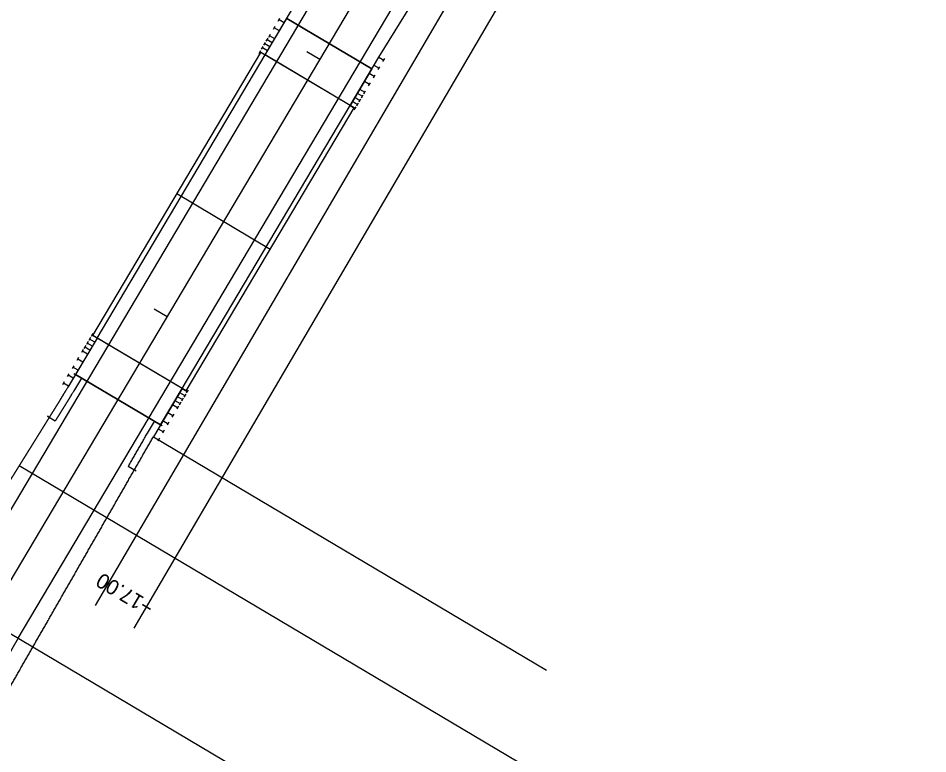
# Model space of a CAD drawing. Extents: x 2138032 to 2141863, y 405316 to 411953.
# Drawn here: x 2140967.3 to 2141271.2, y 410155 to 410400.8 of the extents above; entities that cross this region are included whole.
import ezdxf

# ---------------------------------------------------------------- set-up
doc = ezdxf.new("R2010")
doc.units = 0
for name, color, linetype in [('Prop Approach Slab', 7, 'Continuous'), ('Prop Approach Slab Hatching', 7, 'Continuous'), ('Prop Dimension Text', 7, 'Continuous'), ('Prop EOT', 7, 'Continuous'), ('Prop Guardrail', 7, 'Continuous'), ('Prop Horizontal Alignment', 7, 'Continuous'), ('Prop Horizontal Alignment Station Label', 7, 'Continuous'), ('Prop Horizontal Alignment Tick Small', 7, 'Continuous'), ('Prop Roadway Bridge', 7, 'Continuous'), ('Prop SBG', 7, 'Continuous'), ('Prop Structure Anchor Unit CELL', 7, 'Continuous'), ('Scratch_Level_3', 7, 'Continuous'), ('Scratch_Level_6', 7, 'Continuous')]:
    doc.layers.add(name, color=color, linetype=linetype)

msp = doc.modelspace()

# ---------------------------------------------------------------- linework, layer by layer
at = {"layer": 'Prop Approach Slab'}
for p, q in [((2141049.79, 410388.53), (2141057.02, 410400.71)), ((2141085.4, 410383.87), (2141057.02, 410400.71)), ((2141078.17, 410371.68), (2141085.4, 410383.87)), ((2140993.64, 410293.93), (2140986.41, 410281.75)), ((2141014.79, 410264.9), (2140986.41, 410281.75)), ((2141022.02, 410277.09), (2141014.79, 410264.9))]:
    msp.add_line(p, q, dxfattribs=at)
at = {"layer": 'Prop Approach Slab Hatching'}
for points in [[(2141049.79, 410388.53), (2141057.02, 410400.71), (2141085.4, 410383.87), (2141078.17, 410371.68)], [(2141014.79, 410264.9), (2141022.02, 410277.09), (2140993.64, 410293.93), (2140986.41, 410281.75)]]:
    msp.add_lwpolyline(points, close=True, dxfattribs=at)
at = {"layer": 'Prop EOT'}
for p, q in [((2140946.62, 410205.9), (2141250.61, 410718.06)), ((2140967.26, 410193.65), (2141271.25, 410705.81))]:
    msp.add_line(p, q, dxfattribs=at)
msp.add_arc((2150502.22, 404534.29), 11088, 149.309258, 150.70339, dxfattribs=at)
at = {"layer": 'Prop Guardrail'}
msp.add_line((2141087.74, 410387.81), (2141124.01, 410446.23), dxfattribs=at)
msp.add_open_spline([(2140984.07, 410277.81), (2140983.8, 410277.36), (2140983.52, 410276.92), (2140983.24, 410276.47), (2140983.1, 410276.25), (2140982.96, 410276.02), (2140982.83, 410275.8), (2140982.69, 410275.58), (2140982.55, 410275.35), (2140982.41, 410275.13), (2140982.27, 410274.91), (2140982.13, 410274.68), (2140981.99, 410274.46), (2140981.86, 410274.24), (2140981.72, 410274.01), (2140981.58, 410273.79), (2140981.44, 410273.57), (2140981.3, 410273.34), (2140981.16, 410273.12), (2140981.02, 410272.9), (2140980.89, 410272.67), (2140980.75, 410272.45), (2140980.61, 410272.23), (2140980.47, 410272), (2140980.33, 410271.78), (2140980.19, 410271.56), (2140980.05, 410271.33), (2140979.91, 410271.11), (2140979.78, 410270.89), (2140979.64, 410270.66), (2140979.5, 410270.44), (2140979.36, 410270.22), (2140979.22, 410270), (2140979.08, 410269.77), (2140978.94, 410269.55), (2140978.81, 410269.33), (2140978.67, 410269.1), (2140978.53, 410268.88), (2140978.39, 410268.66), (2140978.25, 410268.43), (2140978.11, 410268.21), (2140977.97, 410267.99), (2140977.84, 410267.76), (2140977.7, 410267.54), (2140977.56, 410267.32), (2140977.42, 410267.09), (2140977.28, 410266.87), (2140977.14, 410266.65), (2140977, 410266.42), (2140976.86, 410266.2), (2140976.73, 410265.98), (2140976.59, 410265.75), (2140976.45, 410265.53), (2140976.31, 410265.31), (2140976.17, 410265.08), (2140976.03, 410264.86), (2140975.89, 410264.64), (2140975.76, 410264.41), (2140975.62, 410264.19), (2140975.48, 410263.97), (2140975.34, 410263.74), (2140975.2, 410263.52), (2140975.06, 410263.3), (2140974.92, 410263.07), (2140974.79, 410262.85), (2140974.65, 410262.63), (2140974.51, 410262.4), (2140974.37, 410262.18), (2140974.23, 410261.96), (2140974.09, 410261.73), (2140973.95, 410261.51), (2140973.81, 410261.29), (2140973.68, 410261.06), (2140973.54, 410260.84), (2140973.4, 410260.62), (2140973.26, 410260.39), (2140973.12, 410260.17), (2140972.98, 410259.95), (2140972.84, 410259.72), (2140972.71, 410259.5), (2140972.57, 410259.28), (2140972.43, 410259.05), (2140972.29, 410258.83), (2140972.15, 410258.61), (2140972.01, 410258.38), (2140971.87, 410258.16), (2140971.74, 410257.94), (2140971.6, 410257.71), (2140971.46, 410257.49), (2140971.32, 410257.27), (2140971.18, 410257.04), (2140971.04, 410256.82), (2140970.9, 410256.6), (2140970.76, 410256.38), (2140970.63, 410256.15), (2140970.49, 410255.93), (2140970.35, 410255.71), (2140970.21, 410255.48), (2140970.07, 410255.26), (2140969.93, 410255.04), (2140969.79, 410254.81), (2140969.66, 410254.59), (2140969.52, 410254.37), (2140969.38, 410254.14), (2140969.24, 410253.92), (2140969.1, 410253.7), (2140968.96, 410253.47), (2140968.82, 410253.25), (2140968.69, 410253.03), (2140968.55, 410252.8), (2140968.41, 410252.58), (2140968.27, 410252.36), (2140968.13, 410252.13), (2140967.99, 410251.91), (2140967.85, 410251.69), (2140967.71, 410251.46), (2140967.58, 410251.24), (2140967.44, 410251.02), (2140967.3, 410250.79), (2140967.16, 410250.57), (2140967.02, 410250.35), (2140966.88, 410250.12), (2140966.74, 410249.9), (2140966.61, 410249.68), (2140966.47, 410249.45), (2140966.33, 410249.23), (2140966.19, 410249.01), (2140966.05, 410248.78), (2140965.91, 410248.56), (2140965.77, 410248.34), (2140965.64, 410248.11), (2140965.5, 410247.89), (2140965.36, 410247.67), (2140965.22, 410247.44), (2140965.08, 410247.22), (2140964.94, 410247), (2140964.8, 410246.77), (2140964.67, 410246.55), (2140964.53, 410246.33), (2140964.39, 410246.1), (2140964.25, 410245.88), (2140964.11, 410245.66), (2140963.97, 410245.43), (2140963.83, 410245.21), (2140963.69, 410244.99), (2140963.56, 410244.76), (2140963.42, 410244.54), (2140963.28, 410244.32), (2140963.14, 410244.09), (2140963, 410243.87), (2140962.86, 410243.65), (2140962.72, 410243.43), (2140962.59, 410243.2), (2140962.45, 410242.98), (2140962.31, 410242.76), (2140962.17, 410242.53), (2140962.03, 410242.31), (2140961.89, 410242.09), (2140961.75, 410241.86), (2140961.62, 410241.64), (2140961.48, 410241.42), (2140961.34, 410241.19), (2140961.2, 410240.97), (2140961.06, 410240.75), (2140960.92, 410240.52), (2140960.78, 410240.3), (2140960.64, 410240.08), (2140960.51, 410239.85), (2140960.37, 410239.63), (2140960.23, 410239.41), (2140960.09, 410239.18), (2140959.95, 410238.96), (2140959.81, 410238.74), (2140959.67, 410238.51), (2140959.54, 410238.29), (2140959.4, 410238.07), (2140959.26, 410237.84), (2140959.12, 410237.62), (2140958.98, 410237.4), (2140958.84, 410237.17), (2140958.7, 410236.95), (2140958.57, 410236.73), (2140958.43, 410236.5), (2140958.29, 410236.28), (2140958.15, 410236.06), (2140958.01, 410235.83), (2140957.87, 410235.61), (2140957.73, 410235.39), (2140957.59, 410235.16), (2140957.46, 410234.94), (2140957.32, 410234.72), (2140957.18, 410234.49), (2140957.04, 410234.27), (2140956.9, 410234.05), (2140956.76, 410233.82), (2140956.62, 410233.6), (2140956.49, 410233.38), (2140956.35, 410233.15), (2140956.21, 410232.93), (2140956.07, 410232.71), (2140955.93, 410232.48), (2140955.79, 410232.26), (2140955.65, 410232.04), (2140955.52, 410231.81), (2140955.38, 410231.59), (2140955.24, 410231.37), (2140955.1, 410231.14), (2140954.96, 410230.92), (2140954.82, 410230.7), (2140954.68, 410230.48), (2140954.54, 410230.25), (2140954.41, 410230.03), (2140954.27, 410229.81), (2140954.13, 410229.58), (2140953.99, 410229.36), (2140953.85, 410229.14), (2140953.71, 410228.91), (2140953.57, 410228.69), (2140953.44, 410228.47), (2140953.3, 410228.24)], degree=3, dxfattribs=at)
for points in [[(2140983.7, 410210.8), (2140984.08, 410211.48), (2140984.47, 410212.16), (2140984.86, 410212.84), (2140985.25, 410213.52), (2140985.64, 410214.19), (2140986.03, 410214.87), (2140986.42, 410215.55), (2140986.81, 410216.23), (2140987.19, 410216.91), (2140987.58, 410217.58), (2140987.97, 410218.26), (2140988.36, 410218.94), (2140988.75, 410219.62), (2140989.14, 410220.29), (2140989.53, 410220.97), (2140989.91, 410221.65), (2140990.3, 410222.33), (2140990.69, 410223.01), (2140991.08, 410223.68), (2140991.47, 410224.36), (2140991.86, 410225.04), (2140992.25, 410225.72), (2140992.63, 410226.4), (2140993.02, 410227.07), (2140993.41, 410227.75), (2140993.8, 410228.43), (2140994.19, 410229.11), (2140994.58, 410229.78), (2140994.97, 410230.46), (2140995.35, 410231.14), (2140995.74, 410231.82), (2140996.13, 410232.5), (2140996.52, 410233.17), (2140996.91, 410233.85), (2140997.3, 410234.53), (2140997.69, 410235.21), (2140998.07, 410235.89), (2140998.46, 410236.56), (2140998.85, 410237.24), (2140999.24, 410237.92), (2140999.63, 410238.6), (2141000.02, 410239.27), (2141000.41, 410239.95), (2141000.79, 410240.63), (2141001.18, 410241.31), (2141001.57, 410241.99), (2141001.96, 410242.66), (2141002.35, 410243.34), (2141002.74, 410244.02), (2141003.13, 410244.7), (2141003.51, 410245.38), (2141003.9, 410246.05), (2141004.29, 410246.73), (2141004.68, 410247.41), (2141005.07, 410248.09), (2141005.46, 410248.76), (2141005.85, 410249.44), (2141006.23, 410250.12), (2141006.62, 410250.8), (2141007.01, 410251.48), (2141007.4, 410252.15), (2141007.79, 410252.83), (2141008.18, 410253.51), (2141008.57, 410254.19), (2141008.95, 410254.87), (2141009.34, 410255.54), (2141009.73, 410256.22), (2141010.12, 410256.9), (2141010.51, 410257.58), (2141010.9, 410258.25), (2141011.29, 410258.93), (2141011.67, 410259.61), (2141012.45, 410260.97)], [(2140955.02, 410160.66), (2140955.4, 410161.34), (2140955.79, 410162.02), (2140956.17, 410162.7), (2140956.56, 410163.38), (2140956.95, 410164.05), (2140957.33, 410164.73), (2140957.72, 410165.41), (2140958.1, 410166.09), (2140958.49, 410166.77), (2140958.88, 410167.44), (2140959.26, 410168.12), (2140959.65, 410168.8), (2140960.04, 410169.48), (2140960.42, 410170.15), (2140960.81, 410170.83), (2140961.2, 410171.51), (2140961.58, 410172.19), (2140961.97, 410172.86), (2140962.36, 410173.54), (2140962.74, 410174.22), (2140963.13, 410174.9), (2140963.52, 410175.57), (2140963.9, 410176.25), (2140964.29, 410176.93), (2140964.68, 410177.61), (2140965.06, 410178.28), (2140965.45, 410178.96), (2140965.84, 410179.64), (2140966.23, 410180.31), (2140966.61, 410180.99), (2140967, 410181.67), (2140967.39, 410182.35), (2140967.77, 410183.02), (2140968.16, 410183.7), (2140968.55, 410184.38), (2140968.94, 410185.05), (2140969.32, 410185.73), (2140969.71, 410186.41), (2140970.1, 410187.09), (2140970.49, 410187.76), (2140970.88, 410188.44), (2140971.26, 410189.12), (2140971.65, 410189.79), (2140972.04, 410190.47), (2140972.43, 410191.15), (2140972.82, 410191.82), (2140973.2, 410192.5), (2140973.59, 410193.18), (2140973.98, 410193.86), (2140974.37, 410194.54), (2140974.76, 410195.21), (2140975.15, 410195.89), (2140975.54, 410196.57), (2140975.92, 410197.25), (2140976.31, 410197.93), (2140976.7, 410198.6), (2140977.09, 410199.28), (2140977.48, 410199.96), (2140977.87, 410200.64), (2140978.26, 410201.31), (2140978.64, 410201.99), (2140979.03, 410202.67), (2140979.42, 410203.35), (2140979.81, 410204.03), (2140980.2, 410204.7), (2140980.59, 410205.38), (2140980.98, 410206.06), (2140981.36, 410206.74), (2140981.75, 410207.42), (2140982.14, 410208.09), (2140982.53, 410208.77), (2140982.92, 410209.45), (2140983.31, 410210.13), (2140983.7, 410210.8)]]:
    msp.add_spline(points, degree=3, dxfattribs=at)
at = {"layer": 'Prop Horizontal Alignment'}
msp.add_line((2140956.94, 410199.77), (2141260.93, 410711.93), dxfattribs=at)
at = {"layer": 'Prop Horizontal Alignment Station Label'}
msp.add_line((2140958.23, 410199.01), (2141164.54, 410076.55), dxfattribs=at)
at = {"layer": 'Prop Horizontal Alignment Tick Small'}
for p, q in [((2141068.06, 410386.98), (2141063.76, 410389.54)), ((2141017.02, 410300.99), (2141012.72, 410303.54))]:
    msp.add_line(p, q, dxfattribs=at)
at = {"layer": 'Prop Roadway Bridge'}
for p, q in [((2140992.25, 410294.76), (2141048.39, 410389.36)), ((2140993.64, 410293.93), (2141049.79, 410388.53)), ((2141079.56, 410370.85), (2141048.39, 410389.36)), ((2141022.02, 410277.09), (2141078.17, 410371.68)), ((2141023.42, 410276.26), (2141079.56, 410370.85)), ((2141051.49, 410323.56), (2141020.32, 410342.06)), ((2141023.42, 410276.26), (2140992.25, 410294.76))]:
    msp.add_line(p, q, dxfattribs=at)
at = {"layer": 'Prop SBG'}
for p, q in [((2140985.81, 410282.1), (2140986.41, 410281.75)), ((2140988.42, 410280.56), (2140986.08, 410276.62)), ((2140977.15, 410267.98), (2140977.01, 410267.75)), ((2140979.61, 410266.21), (2140977.01, 410267.75)), ((2140977.74, 410267.62), (2140977.61, 410267.4)), ((2141010.45, 410262.16), (2141012.79, 410266.09)), ((2141015.39, 410264.55), (2141014.79, 410264.9)), ((2141006.68, 410249.49), (2141004.05, 410250.99))]:
    msp.add_line(p, q, dxfattribs=at)
msp.add_open_spline([(2140986.05, 410276.58), (2140985.78, 410276.13), (2140985.5, 410275.69), (2140985.22, 410275.24), (2140985.08, 410275.02), (2140984.94, 410274.79), (2140984.81, 410274.57), (2140984.67, 410274.35), (2140984.53, 410274.12), (2140984.39, 410273.9), (2140984.25, 410273.68), (2140984.11, 410273.45), (2140983.97, 410273.23), (2140983.84, 410273.01), (2140983.7, 410272.78), (2140983.56, 410272.56), (2140983.42, 410272.34), (2140983.28, 410272.12), (2140983.14, 410271.89), (2140983, 410271.67), (2140982.86, 410271.45), (2140982.73, 410271.22), (2140982.59, 410271), (2140982.45, 410270.78), (2140982.31, 410270.55), (2140982.17, 410270.33), (2140982.03, 410270.11), (2140981.89, 410269.88), (2140981.76, 410269.66), (2140981.62, 410269.44), (2140981.48, 410269.21), (2140981.34, 410268.99), (2140981.2, 410268.77), (2140981.06, 410268.54), (2140980.92, 410268.32), (2140980.79, 410268.1), (2140980.65, 410267.87), (2140980.51, 410267.65), (2140980.37, 410267.43), (2140980.23, 410267.2), (2140980.09, 410266.98), (2140979.95, 410266.76), (2140979.81, 410266.53), (2140979.75, 410266.43), (2140979.68, 410266.32), (2140979.61, 410266.21)], degree=3, dxfattribs=at)
msp.add_spline([(2141004.05, 410250.99), (2141004.21, 410251.28), (2141004.6, 410251.96), (2141004.99, 410252.64), (2141005.38, 410253.31), (2141005.77, 410253.99), (2141006.16, 410254.67), (2141006.54, 410255.35), (2141006.93, 410256.02), (2141007.32, 410256.7), (2141007.71, 410257.38), (2141008.1, 410258.06), (2141008.49, 410258.74), (2141008.88, 410259.41), (2141009.26, 410260.09), (2141009.65, 410260.77), (2141010.43, 410262.13)], degree=3, dxfattribs=at)
at = {"layer": 'Prop Structure Anchor Unit CELL'}
for p, q in [((2141049.79, 410388.53), (2141059.36, 410404.65)), ((2141054.16, 410399.8), (2141054.74, 410400.79)), ((2141056.17, 410399.28), (2141054.45, 410400.3)), ((2141052.56, 410397.12), (2141053.15, 410398.1)), ((2141054.57, 410396.59), (2141052.85, 410397.61)), ((2141049.37, 410391.74), (2141049.96, 410392.73)), ((2141050.17, 410393.09), (2141050.75, 410394.07)), ((2141052.18, 410392.56), (2141050.46, 410393.58)), ((2141050.97, 410394.43), (2141051.55, 410395.41)), ((2141052.98, 410393.9), (2141051.26, 410394.92)), ((2141047.78, 410389.05), (2141048.36, 410390.04)), ((2141049.79, 410388.53), (2141048.07, 410389.55)), ((2141048.57, 410390.4), (2141049.16, 410391.38)), ((2141050.59, 410389.87), (2141048.87, 410390.89)), ((2141051.38, 410391.21), (2141049.66, 410392.23)), ((2141078.17, 410371.68), (2141087.74, 410387.81)), ((2141087.74, 410387.81), (2141089.46, 410386.79)), ((2141089.16, 410386.29), (2141089.75, 410387.28)), ((2141086.14, 410385.12), (2141087.86, 410384.1)), ((2141087.57, 410383.61), (2141088.15, 410384.59)), ((2141084.55, 410382.43), (2141086.27, 410381.41)), ((2141085.97, 410380.92), (2141086.56, 410381.9)), ((2141082.95, 410379.74), (2141084.67, 410378.72)), ((2141084.38, 410378.23), (2141084.96, 410379.22)), ((2141079.76, 410374.37), (2141081.48, 410373.35)), ((2141080.56, 410375.71), (2141082.28, 410374.69)), ((2141081.36, 410377.06), (2141083.08, 410376.04)), ((2141081.99, 410374.2), (2141082.57, 410375.19)), ((2141082.78, 410375.54), (2141083.37, 410376.53)), ((2141078.17, 410371.68), (2141079.89, 410370.66)), ((2141078.96, 410373.03), (2141080.68, 410372.01)), ((2141080.39, 410371.51), (2141080.98, 410372.5)), ((2141081.19, 410372.86), (2141081.77, 410373.84)), ((2141079.59, 410370.17), (2141080.18, 410371.15)), ((2140992.22, 410295.45), (2140991.63, 410294.46)), ((2140993.64, 410293.93), (2140984.07, 410277.81)), ((2140990.62, 410292.76), (2140990.04, 410291.77)), ((2140992.05, 410291.25), (2140990.33, 410292.27)), ((2140991.42, 410294.1), (2140990.83, 410293.12)), ((2140992.85, 410292.59), (2140991.13, 410293.61)), ((2140993.64, 410293.93), (2140991.92, 410294.95)), ((2140989.03, 410290.07), (2140988.44, 410289.09)), ((2140990.45, 410288.56), (2140988.73, 410289.58)), ((2140989.82, 410291.42), (2140989.24, 410290.43)), ((2140991.25, 410289.9), (2140989.53, 410290.92)), ((2140987.43, 410287.38), (2140986.85, 410286.4)), ((2140988.86, 410285.87), (2140987.14, 410286.89)), ((2140985.84, 410284.7), (2140985.25, 410283.71)), ((2140987.26, 410283.18), (2140985.54, 410284.21)), ((2140984.24, 410282.01), (2140983.66, 410281.03)), ((2140985.67, 410280.5), (2140983.95, 410281.52)), ((2140982.65, 410279.32), (2140982.06, 410278.34)), ((2140984.07, 410277.81), (2140982.35, 410278.83)), ((2141022.02, 410277.09), (2141012.45, 410260.97)), ((2141022.02, 410277.09), (2141023.74, 410276.07)), ((2141020.43, 410274.4), (2141022.15, 410273.38)), ((2141021.22, 410275.75), (2141022.94, 410274.73)), ((2141023.24, 410275.22), (2141022.65, 410274.23)), ((2141024.03, 410276.56), (2141023.45, 410275.58)), ((2141018.83, 410271.72), (2141020.55, 410270.69)), ((2141019.63, 410273.06), (2141021.35, 410272.04)), ((2141020.84, 410271.19), (2141020.26, 410270.2)), ((2141021.64, 410272.53), (2141021.06, 410271.55)), ((2141022.44, 410273.87), (2141021.85, 410272.89)), ((2141017.24, 410269.03), (2141018.96, 410268.01)), ((2141019.25, 410268.5), (2141018.66, 410267.51)), ((2141015.64, 410266.34), (2141017.36, 410265.32)), ((2141017.65, 410265.81), (2141017.07, 410264.83)), ((2141014.05, 410263.65), (2141015.77, 410262.63)), ((2141016.06, 410263.13), (2141015.47, 410262.14)), ((2141012.45, 410260.97), (2141014.17, 410259.95)), ((2141014.46, 410260.44), (2141013.88, 410259.45))]:
    msp.add_line(p, q, dxfattribs=at)
at = {"layer": 'Scratch_Level_3'}
for p, q in [((2141139.73, 410455.24), (2140992.96, 410204.62)), ((2141152.68, 410447.66), (2141005.91, 410197.04))]:
    msp.add_line(p, q, dxfattribs=at)
at = {"layer": 'Scratch_Level_6'}
for p, q in [((2141012.45, 410260.97), (2141143.84, 410182.98)), ((2141164.96, 410134.11), (2140967.59, 410251.26))]:
    msp.add_line(p, q, dxfattribs=at)

# ---------------------------------------------------------------- texts
at = {"layer": 'Prop Dimension Text'}
msp.add_text('+17.00', height=5, rotation=149.3093, dxfattribs=at).set_placement((2141013.03, 410205.18))

doc.saveas('drawing.dxf')
